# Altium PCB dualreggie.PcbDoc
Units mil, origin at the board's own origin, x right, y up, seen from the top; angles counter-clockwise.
Board outline 735 x 480 mil, 2 copper layers (L1, L2), stack 62.8 mil thick; 24 components, 10 nets, 53 pads, 8 vias.
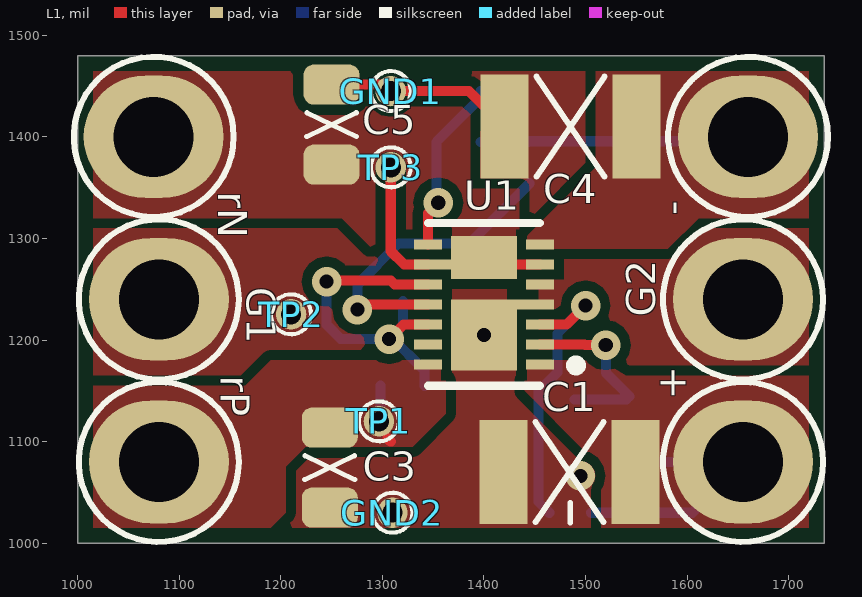
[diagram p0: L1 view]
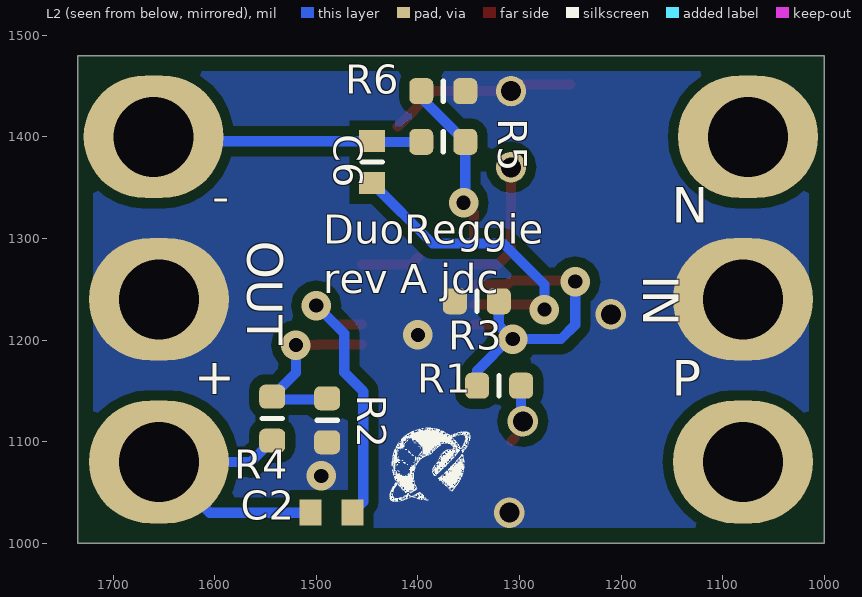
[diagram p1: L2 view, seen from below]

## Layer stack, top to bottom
Top Solder: solder mask 0.1, Solder Resist, Dk 0
L1: signal copper 1.4
Core: dielectric 60, FR-4, Dk 4.6
L2: signal copper 1.4
Bottom Solder: solder mask 0.1, Solder Resist, Dk 0

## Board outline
1000,1000 1000,1480 1735,1480 1735,1000

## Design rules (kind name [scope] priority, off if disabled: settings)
BoardOutlineClearance [All] p1: gap=15 ignorepadtopadclearanceinfootprint=FALSE
Clearance [All] p1: gap=10 ignorepadtopadclearanceinfootprint=FALSE except(0: Arc-Hole Track-Hole SMDPad-Hole THPad-Hole Via-Hole Fill-Hole Poly-Hole Region-Hole Text-Hole)
HoleSize [All] p1: absolutevalues=TRUE maxlimit=265 minlimit=13 maxpercent=80.000 minpercent=20.000
HoleToHoleClearance [All] p1: gap=10 allowstackedmicrovias=FALSE
MinimumAnnularRing [All] p1: minimumring=7
MinimumSolderMaskSliver [All] p1: minsoldermaskwidth=0
PlaneConnect [All] p1: planeconnectstyle=Direct reliefexpansion=20 reliefentries=4 reliefconductorwidth=10 reliefairgap=10
PolygonConnect [All] p1: connectstyle=Direct reliefconductorwidth=10 reliefentries=4 polygonreliefangle="90 Angle" airgapwidth=10
RoutingVias [All] p1: holewidth=28 width=50 viastyle="Through Hole" minholewidth=28 minwidth=50 maxholewidth=28 maxwidth=50
SilkToSilkClearance [All] p1: silktosilkclearance=0
SilkToSolderMaskClearance [IsPad] p1: minsilkscreentomaskgap=6 clearancetoexposedcopper=TRUE
SolderMaskExpansion [All] p1: expansion=4
Width [All] p1: maxlimit=10 minlimit=10 preferedwidth=10
24 further rules are at their usual default settings.

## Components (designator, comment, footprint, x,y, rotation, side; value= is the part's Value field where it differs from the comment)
+ "TP 0.5mm" SP2.0 1655,1080 r180 top (schematic designator V+)
- "TP 0.5mm" SP2.0 1660,1400 r180 top (schematic designator V-)
C1 "10uF" CC1210N1X 1484.33,1070 r0 top
C2 "10nF" CC0402N1X 1485,1030 r0 bottom
C3 "22uF" CC0805N1R 1248.29,1074.41 r90 top
C4 "10uF" CC1210N1X 1485,1410 r0 top
C5 "22uF" CC0805N1R 1250,1412 r90 top
C6 "10nF" CC0402N1X 1445,1375 r90 bottom
G1 "TP 0.5mm" SP2.0 1080,1240 r180 top
G2 "TP 0.5mm" SP2.0 1655,1240 r0 top
GND1 "TP 0.5mm" TPH0.5S 1308.35,1445 r0 top
GND2 "TP 0.5mm" TPH0.5S 1310,1030 r0 top
R1 "4k7" RC0402N1R 1320,1155 r180 bottom
R2 "82k" RC0402N1R 1489.32,1120.98 r90 bottom
R3 "4k7" RC0402N1R 1342.01,1238.11 r180 bottom
R4 "82k" RC0402N1R 1543.38,1122.67 r270 bottom
R5 "82k" RC0402N1R 1375,1395 r0 bottom
R6 "82k" RC0402N1R 1375,1445 r0 bottom
rN "TP 0.5mm" SP2.0 1075,1400 r0 top (schematic designator RAWN)
rP "TP 0.5mm" SP2.0 1080,1080 r0 top (schematic designator RAWP)
TP1 "TP 0.5mm" TPH0.5S 1296.69,1120 r90 top
TP2 "TP 0.5mm" TPH0.5S 1210.15,1225.31 r90 top
TP3 "TP 0.5mm" TPH0.5S 1308.35,1370 r90 top
U1 "LT3032MPDE#PBF" LT-DE14MA-14_V 1400,1235 r180 top

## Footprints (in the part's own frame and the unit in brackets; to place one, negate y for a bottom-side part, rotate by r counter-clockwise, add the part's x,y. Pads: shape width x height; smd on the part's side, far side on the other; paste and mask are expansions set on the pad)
CC0402N1X [mm] "Chip capacitor 0402"
  rect 0.55x0.65 smd mask+0.025: 1(-0.525,0) 2(0.525,0)
  body extent -0.51,-0.25 0.51,0.25, height 0.5
CC0805N1R [mm]
  rrect50% 1x1.4 smd: 1(-1,0) 2(1,0)
  silkscreen extent -0.3,-0.63 0.3,0.63, body extent -1,-0.63 1,0.63, height 1
CC1210N1X [mm] "Chip capacitor 1210"
  rect 1.2x2.6 smd: 1(-1.65,0) 2(1.65,0)
  silkscreen extent -0.85,-1.25 0.85,1.25, body extent -1.6,-1.25 1.6,1.25, height 1.5
LT-DE14MA-14_V [mm] "DE14MA, 14-Leads, Body 4x3mm, Pitch 0.5mm"
  rect 0.7x0.25 smd: 1(-1.4,1.5) 2(-1.4,1) 3(-1.4,0.5) 4(-1.4,0) 5(-1.4,-0.5) 6(-1.4,-1) 7(-1.4,-1.5) 8(1.4,-1.5) 9(1.4,-1) 10(1.4,-0.5) 11(1.4,0) 12(1.4,0.5) 13(1.4,1) 14(1.4,1.5)
  rect 1.65x1.78 smd: 15(0,0.765)
  rect 1.65x1.07 smd: 16(0,-1.17)
  rect 0.3x0.25 smd: ""(-0.97,0)
  rect 0.5x0.25 smd: ""(0.9,-1)
  silkscreen extent -2.43,1.4 -2.18,1.65, body extent -1.5,-2 1.5,2, height 0.75
RC0402N1R [mm]
  rrect50% 0.6x0.65 smd: 1(-0.55,0) 2(0.55,0)
  silkscreen extent 0,-0.25 0,0.25, body extent -0.51,-0.25 0.51,0.25, height 0.36
SP2.0 [mm] "Solder Pin 2.0mm"
  oval 3.5x3.068 hole 2: 1(0,0)
  silkscreen extent -2,-2 2,2
TPH0.5S [mil] "Test point TH 0.5mm slim"
  round 30 hole 19.68: 1(0,0)
  silkscreen extent -20,-20 20,20

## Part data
+ - G1 G2 GND1 GND2 rN rP TP1 TP2 TP3: library part ELE-TP0.5S, "Test Point 0.5mm Slim"
C1 C4: library part CAPCC1210_10U_50VX7R, "Capacitor chip ceramic 1210 50V X7R", Manufacturer=TDK, Manufacturer No=GRM32ER71H106KA12L, Package="Cap Chip 1210", Supplier Part Number 1=29X1411, Voltage rating=50V
C2 C6: library part CAPCC0402_1_10.0N_50VX7R, "Capacitor chip ceramic 0402 50V X7R", Manufacturer=Murata, Manufacturer No=GRM155R71H103KA88J, Package="Cap Chip 0402", Supplier Part Number 1=81-GRM155R71H103KA8J, Voltage rating=50V
C3 C5: library part CAPCC0805_22U_16VX7R, "Capacitor chip ceramic 0805 16V X7R", Manufacturer=Murata, Manufacturer No=GRM219R61C226ME15L, Package="Cap Chip 0805", Supplier Part Number 1=490-9952-1-ND, Voltage rating=16V
R1 R3: library part RES0402-1-4.7K-1%100PPM, "Chip Resistor 0402 62.5mW 1% 100ppm", Manufacturer=Panasonic, Manufacturer No=ERJ-2RKF4701X, Package="Res Chip 0402", Supplier Part Number 1=64R5288
R2 R4 R5 R6: library part RES0402-1-82K-1%100PPM, "Chip Resistor 0402 62.5mW 1% 100ppm", Manufacturer=Panasonic, Manufacturer No=ERJ-2RKF8202X, Package="Res Chip 0402", Supplier Part Number 1=53W8367
U1: "Dual 150 mA Positive / Negative Low Noise Low Dropout Linear Regulator, +/-2.3 to +/-20 V Vin, Adjustable Vout, 14-pin SON (DE14MA-14), -55 to 125 degC, Pb-Free", Dropout Voltage(V)=0.3, Manufacturer="Linear Technology", Output Voltage=Adj,-Adj, Shutdown Current(uA)=0.1, Supplier Part Number 1=LT3032MPDE#PBF-ND

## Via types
v1: diameter 29, hole 14, L1 to L2, 8 vias

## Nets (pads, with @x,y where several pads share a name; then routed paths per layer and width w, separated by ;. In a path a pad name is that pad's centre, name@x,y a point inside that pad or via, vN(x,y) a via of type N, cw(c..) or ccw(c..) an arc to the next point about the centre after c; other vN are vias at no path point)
+RAW: C3.2 R1.2 rP.1 TP1.1 U1.14 | length 49.7
  L1 w10: 1305,1103.35 1308.35,1100
  L2 w10: TP1.1@1298.35,1110 R1.2
-RAW: C5.1 rN.1 TP3.1 U1.6 U1.9 U1.16 | length 182.4
  L1 w10: TP3.1 1308.35,1287.5 1321.48,1274.37 U1.9 ; U1.16 1406.69,1274.37 U1.6
ADN: R5.1 R6.2 U1.8 | length 180.5
  L1 w10: U1.8 1344.88,1324.88 v1(1355,1335)
  L2 w10: v1(1355,1335) 1355,1333.31 1353.35,1331.65 R5.1 1396.65,1438.31 R6.2
ADP: R2.2 R4.1 U1.2 | length 182.3
  L1 w10: U1.2 1498.74,1195.63 1499.37,1195 v1(1520,1195)
  L2 w10: R2.2@1489.32,1141.4 1540.45,1141.4 1539.9,1143.33 R4.1@1538.9,1146.83 ; v1(1520,1195) 1520,1167.7 R4.1
GND: C1.1 C3.1 C4.1 C5.2 G1.1 G2.1 GND1.1 GND2.1 R2.1 R3.1 R6.1 TP2.1 U1.4 U1.5 U1.15 | length 187.2
  L1 w10: C5.2 1301.98,1451.37 GND1.1 1385.04,1445 C4.1
  other v1: 1495,1066.2 1400,1205
NetC2_1: C2.1 U1.3 | length 280
  L1 w10: U1.3 1481.42,1215.32 v1(1500,1233.89)
  L2 w10: C2.1 1453.78,1040.55 1453.78,1149.46 1472.5,1168.18 1472.5,1206.39 v1(1500,1233.89)
NetC6_1: C6.1 U1.11 | length 306.9
  L1 w10: v1(1275.46,1230) 1280.46,1235 U1.11
  L2 w10: v1(1275.46,1230) 1275.46,1254.48 1315.97,1295 1385.67,1295 C6.1
NetR1_1: R1.1 R3.2 U1.10 U1.12 | length 364.2
  L1 w10: v1@1247.96,1254.68 v1(1245.15,1257.5) 1246.15,1258.5 1308.33,1258.5 1312.15,1254.68 U1.10 ; v1(1306.62,1200.94) 1320.99,1215.32 U1.12
  L2 w10: v1(1245.15,1257.5) 1245.15,1214.85 1259.06,1200.94 v1(1306.62,1200.94) v1@1308.55,1202.88 ; R3.2 1320.35,1214.68 v1@1308.55,1202.88 ; R1.1 1341.65,1169.77 v1@1308.55,1202.88
V+: +.1 C1.2 C2.2 R4.2 U1.1 | length 291.5
  L2 w10: C2.2 1605,1030 +.1 1565,1080 1565,1079.4 R4.2 R4.2@1543.18,1100.82
V-: -.1 C4.2 C6.2 R5.2 U1.7 | length 265.4
  L2 w10: R5.2 1444.33,1395 C6.2 1655.67,1395.67 -.1
pads on no net: U1. U1.13

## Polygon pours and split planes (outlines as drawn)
GND on L1 "L1-GND" (solid, pour order 14): 1000,1000 1735,1000 1735,1480 1000,1480
-RAW on L1 "L1--RAW" (solid, pour order 0): 1000,1480 1005,1475 1435,1475 1435,1260 1430,1255 1325,1255 1260,1320 1000,1320
V+ on L1 "L1-V+" (solid, pour order 12): 1740,995 1735,1000 1735,1165 1550,1165 1540,1165 1515,1180 1440,1180 1440,1150 1515.52,1074.48 1515.52,1014.48 1535,995
V- on L1 "L1-V-" (solid, pour order 8): 1735,1480 1521.05,1480 1510,1468.95 1510,1370 1448.98,1308.98 1438.19,1298.19 1438.19,1289.66 1580.89,1289.66 1611.22,1320 1735,1320
+RAW on L1 "L1-+RAW" (solid, pour order 4): 1000,1000 1175,1000 1205,1030 1205,1075.46 1224.54,1095 1330,1095 1362.5,1127.5 1362.5,1180 1190,1180 1165,1155 1000,1155
GND on L2 "L2-GND" (solid, pour order 10): 1000,1480 1740,1480 1735,1475 1735,1000 1000,1000

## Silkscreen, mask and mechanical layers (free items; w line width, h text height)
Top Overlay:
  lines w8: 1345,1155 1455,1155 ; 1345,1315 1455,1315
Bottom Overlay:
  drawing of 177 lines, arcs and shapes, not listed
  text "-" at 1585,1313.56 h60
  text "N" at 1150,1303.56 h60
  text "OUT" at 1580,1297.78 h60 r90
  text "IN" at 1190,1263.89 h60 r90
  text "DuoReggie  / rev A jdc" at 1493.35,1236.61 h49
  text "+" at 1580,1135 h60
  text "P" at 1150,1133.56 h60
Mechanical 1:
  the board outline again, w10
